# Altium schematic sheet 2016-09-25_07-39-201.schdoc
size 262 x 161 mm; SheetNumber: 1; SheetTotal: 1
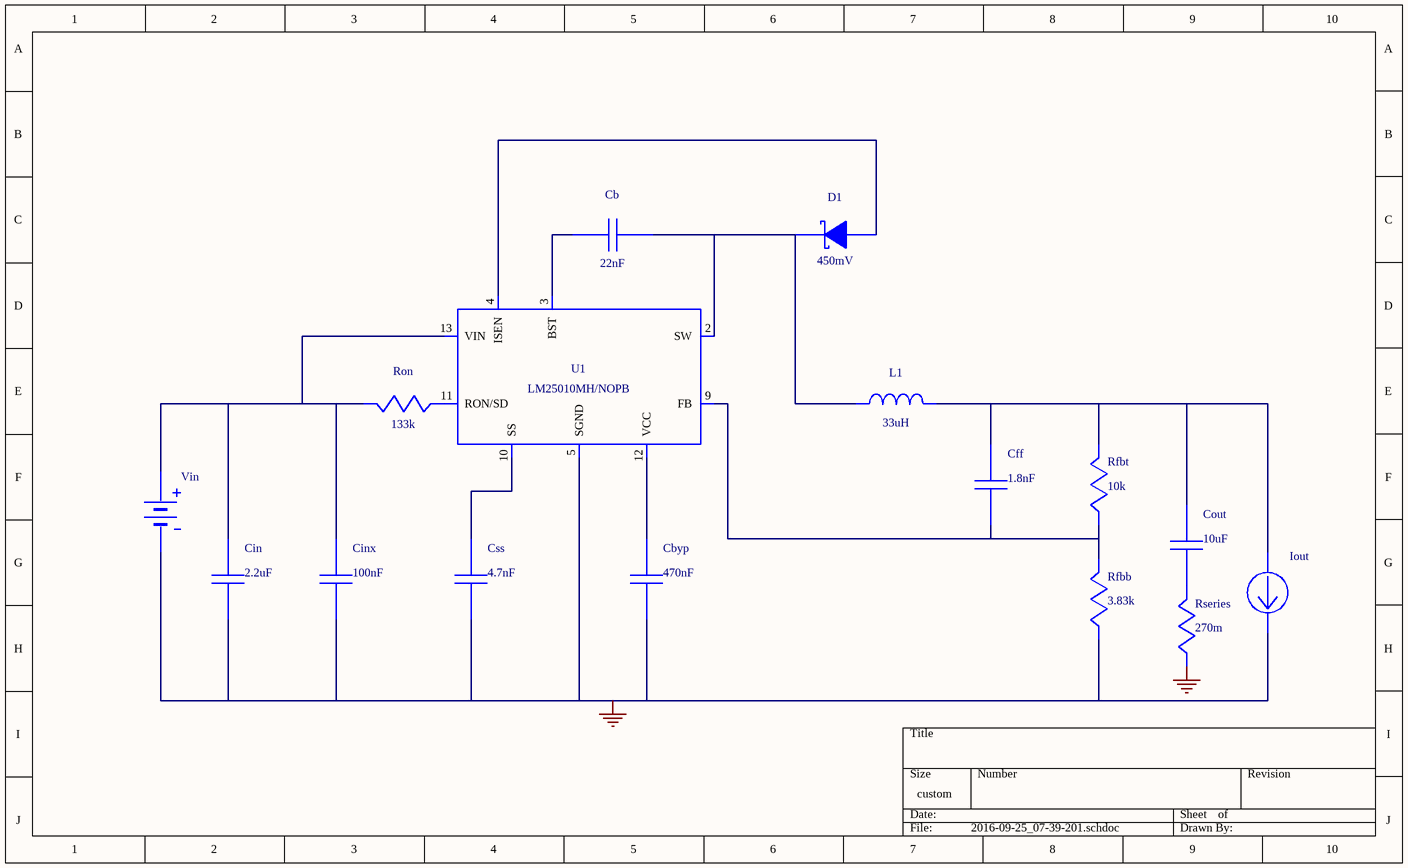
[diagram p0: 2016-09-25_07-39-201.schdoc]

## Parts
Cb  value 22nF  (hidden comment: GRM155R61C223KA01D)
Cbyp  value 470nF  (hidden comment: 0805YC474KAT2A)
Cff  value 1.8nF  (hidden comment: C1206C182K5RACTU)
Cin  value 2.2uF  (hidden comment: GRM31CR71H225KA88L)
Cinx  value 100nF  (hidden comment: C0603C104K5RACTU)
Cout  value 10uF  (hidden comment: GRM21BR61C106KE15L)
Css  value 4.7nF  (hidden comment: GRM155R61C472KA01D)
D1  value 450mV  (hidden comment: 1N5819HW-7-F)
Iout  WB_CURRENT_LOAD  (value not drawn)
L1  value 33uH  (hidden comment: SRN8040-330M)
Rfbb  value 3.83k  (hidden comment: CRCW04023K83FKED)
Rfbt  value 10k  (hidden comment: CRCW040210K0FKED)
Ron  value 133k  (hidden comment: CRCW0402133KFKED)
Rseries  value 270m  (hidden comment: ERJ-3RQFR27V)
U1  LM25010MH/NOPB
Vin  WB_BATTERY  (value not drawn)

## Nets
0: Cbyp.2 Cin.2 Cinx.2 Css.2 Iout.2(-) Rfbb.2 Rseries.2 U1.1(NC) U1.5(SGND) U1.6(RTN) U1.7(NC) U1.8(NC) U1.14(NC) U1.15(DAP) Vin.2(-)
NetCb_1: Cb.1 D1.1(K) L1.1 U1.2(SW)
NetCb_2: Cb.2 U1.3(BST)
NetCbyp_1: Cbyp.1 U1.12(VCC)
NetCff_1: Cff.1 Cout.1 Iout.1(+) L1.2 Rfbt.1
NetCff_2: Cff.2 Rfbb.1 Rfbt.2 U1.9(FB)
NetCin_1: Cin.1 Cinx.1 Ron.1 U1.13(VIN) Vin.1(+)
NetCout_2: Cout.2 Rseries.1
NetCss_1: Css.1 U1.10(SS)
NetD1_2: D1.2(A) U1.4(ISEN)
NetRon_2: Ron.2 U1.11(RON/SD)

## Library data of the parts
Cb = GRM155R61C223KA01D: GRM155R61C223KA0; Manufacturer Name: MuRata
Cbyp = 0805YC474KAT2A: Manufacturer Name: AVX
Cff = C1206C182K5RACTU: Manufacturer Name: Kemet
Cin = GRM31CR71H225KA88L: GRM31CR71H225KA8; Manufacturer Name: MuRata
Cinx = C0603C104K5RACTU: Manufacturer Name: Kemet
Cout = GRM21BR61C106KE15L: GRM21BR61C106KE1; Manufacturer Name: MuRata
Css = GRM155R61C472KA01D: GRM155R61C472KA0; Manufacturer Name: MuRata
D1 = 1N5819HW-7-F: Manufacturer Name: Diodes Inc.
L1 = SRN8040-330M: Manufacturer Name: Bourns
Rfbb = CRCW04023K83FKED: Manufacturer Name: Vishay-Dale
Rfbt = CRCW040210K0FKED: Manufacturer Name: Vishay-Dale
Ron = CRCW0402133KFKED: Manufacturer Name: Vishay-Dale
Rseries = ERJ-3RQFR27V: Manufacturer Name: Panasonic
U1 = LM25010MH/NOPB: Manufacturer Name: Texas Instruments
